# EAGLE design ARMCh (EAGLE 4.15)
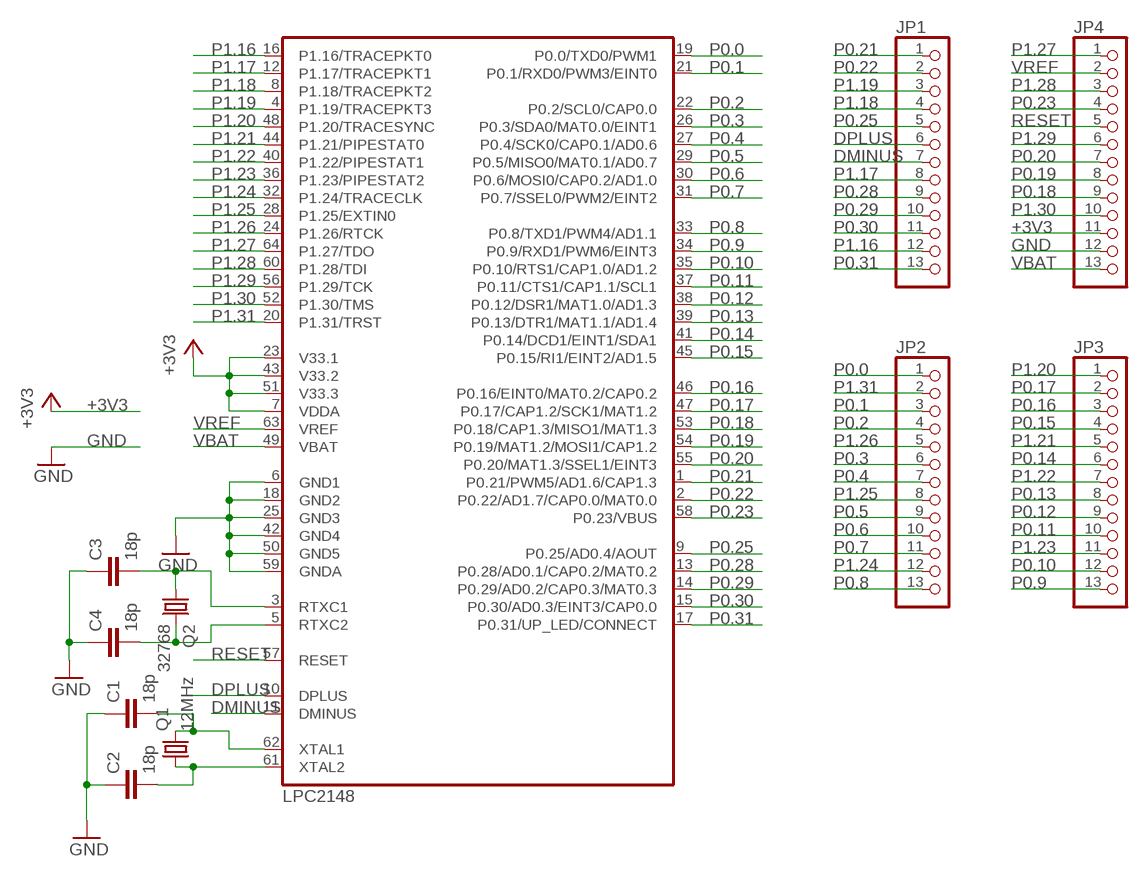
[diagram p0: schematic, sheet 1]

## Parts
C1  18p  C-EUC0805  [C0805]
C2  18p  C-EUC0805  [C0805]
C3  18p  C-EUC0805  [C0805]
C4  18p  C-EUC0805  [C0805]
JP1  PINHD-1X13  [1X13]
JP2  PINHD-1X13  [1X13]
JP3  PINHD-1X13  [1X13]
JP4  PINHD-1X13  [1X13]
LPC2148  LPC2146  [LQFP64]
Q1  12MHz  CRYTALHC49S  [HC49/S]
Q2  32768  CRYTALHC49U70  [HC49U70]

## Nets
+3V3: JP4.11 LPC2148.7(VDDA) LPC2148.23(V33.1) LPC2148.43(V33.2) LPC2148.51(V33.3)
DMINUS: JP1.7 LPC2148.11(DMINUS)
DPLUS: JP1.6 LPC2148.10(DPLUS)
GND: C1.1 C2.1 C3.1 C4.1 JP4.12 LPC2148.6(GND1) LPC2148.18(GND2) LPC2148.25(GND3) LPC2148.42(GND4) LPC2148.50(GND5) LPC2148.59(GNDA)
N$1: C1.2 LPC2148.62(XTAL1) Q1.2
N$3: C2.2 LPC2148.61(XTAL2) Q1.1
N$4: C3.2 LPC2148.3(RTXC1) Q2.1
N$5: C4.2 LPC2148.5(RTXC2) Q2.2
P0.0: JP2.1 LPC2148.19(P0.0/TXD0/PWM1)
P0.1: JP2.3 LPC2148.21(P0.1/RXD0/PWM3/EINT0)
P0.2: JP2.4 LPC2148.22(P0.2/SCL0/CAP0.0)
P0.3: JP2.6 LPC2148.26(P0.3/SDA0/MAT0.0/EINT1)
P0.4: JP2.7 LPC2148.27(P0.4/SCK0/CAP0.1/AD0.6)
P0.5: JP2.9 LPC2148.29(P0.5/MISO0/MAT0.1/AD0.7)
P0.6: JP2.10 LPC2148.30(P0.6/MOSI0/CAP0.2/AD1.0)
P0.7: JP2.11 LPC2148.31(P0.7/SSEL0/PWM2/EINT2)
P0.8: JP2.13 LPC2148.33(P0.8/TXD1/PWM4/AD1.1)
P0.9: JP3.13 LPC2148.34(P0.9/RXD1/PWM6/EINT3)
P0.10: JP3.12 LPC2148.35(P0.10/RTS1/CAP1.0/AD1.2)
P0.11: JP3.10 LPC2148.37(P0.11/CTS1/CAP1.1/SCL1)
P0.12: JP3.9 LPC2148.38(P0.12/DSR1/MAT1.0/AD1.3)
P0.13: JP3.8 LPC2148.39(P0.13/DTR1/MAT1.1/AD1.4)
P0.14: JP3.6 LPC2148.41(P0.14/DCD1/EINT1/SDA1)
P0.15: JP3.4 LPC2148.45(P0.15/RI1/EINT2/AD1.5)
P0.16: JP3.3 LPC2148.46(P0.16/EINT0/MAT0.2/CAP0.2)
P0.17: JP3.2 LPC2148.47(P0.17/CAP1.2/SCK1/MAT1.2)
P0.18: JP4.9 LPC2148.53(P0.18/CAP1.3/MISO1/MAT1.3)
P0.19: JP4.8 LPC2148.54(P0.19/MAT1.2/MOSI1/CAP1.2)
P0.20: JP4.7 LPC2148.55(P0.20/MAT1.3/SSEL1/EINT3)
P0.21: JP1.1 LPC2148.1(P0.21/PWM5/AD1.6/CAP1.3)
P0.22: JP1.2 LPC2148.2(P0.22/AD1.7/CAP0.0/MAT0.0)
P0.23: JP4.4 LPC2148.58(P0.23/VBUS)
P0.25: JP1.5 LPC2148.9(P0.25/AD0.4/AOUT)
P0.28: JP1.9 LPC2148.13(P0.28/AD0.1/CAP0.2/MAT0.2)
P0.29: JP1.10 LPC2148.14(P0.29/AD0.2/CAP0.3/MAT0.3)
P0.30: JP1.11 LPC2148.15(P0.30/AD0.3/EINT3/CAP0.0)
P0.31: JP1.13 LPC2148.17(P0.31/UP_LED/CONNECT)
P1.16: JP1.12 LPC2148.16(P1.16/TRACEPKT0)
P1.17: JP1.8 LPC2148.12(P1.17/TRACEPKT1)
P1.18: JP1.4 LPC2148.8(P1.18/TRACEPKT2)
P1.19: JP1.3 LPC2148.4(P1.19/TRACEPKT3)
P1.20: JP3.1 LPC2148.48(P1.20/TRACESYNC)
P1.21: JP3.5 LPC2148.44(P1.21/PIPESTAT0)
P1.22: JP3.7 LPC2148.40(P1.22/PIPESTAT1)
P1.23: JP3.11 LPC2148.36(P1.23/PIPESTAT2)
P1.24: JP2.12 LPC2148.32(P1.24/TRACECLK)
P1.25: JP2.8 LPC2148.28(P1.25/EXTIN0)
P1.26: JP2.5 LPC2148.24(P1.26/RTCK)
P1.27: JP4.1 LPC2148.64(P1.27/TDO)
P1.28: JP4.3 LPC2148.60(P1.28/TDI)
P1.29: JP4.6 LPC2148.56(P1.29/TCK)
P1.30: JP4.10 LPC2148.52(P1.30/TMS)
P1.31: JP2.2 LPC2148.20(P1.31/TRST)
RESET: JP4.5 LPC2148.57(RESET)
VBAT: JP4.13 LPC2148.49(VBAT)
VREF: JP4.2 LPC2148.63(VREF)

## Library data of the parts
C1-C4 = rcl:C-EU: CAPACITOR, European symbol
JP1-JP4 = pinhead:PINHD-1X13: PIN HEADER
LPC2148 = lpc2148:LPC2146: Philips LPC2146 ARM7
Q1 Q2 = crystal:CRYTAL: CRYSTAL

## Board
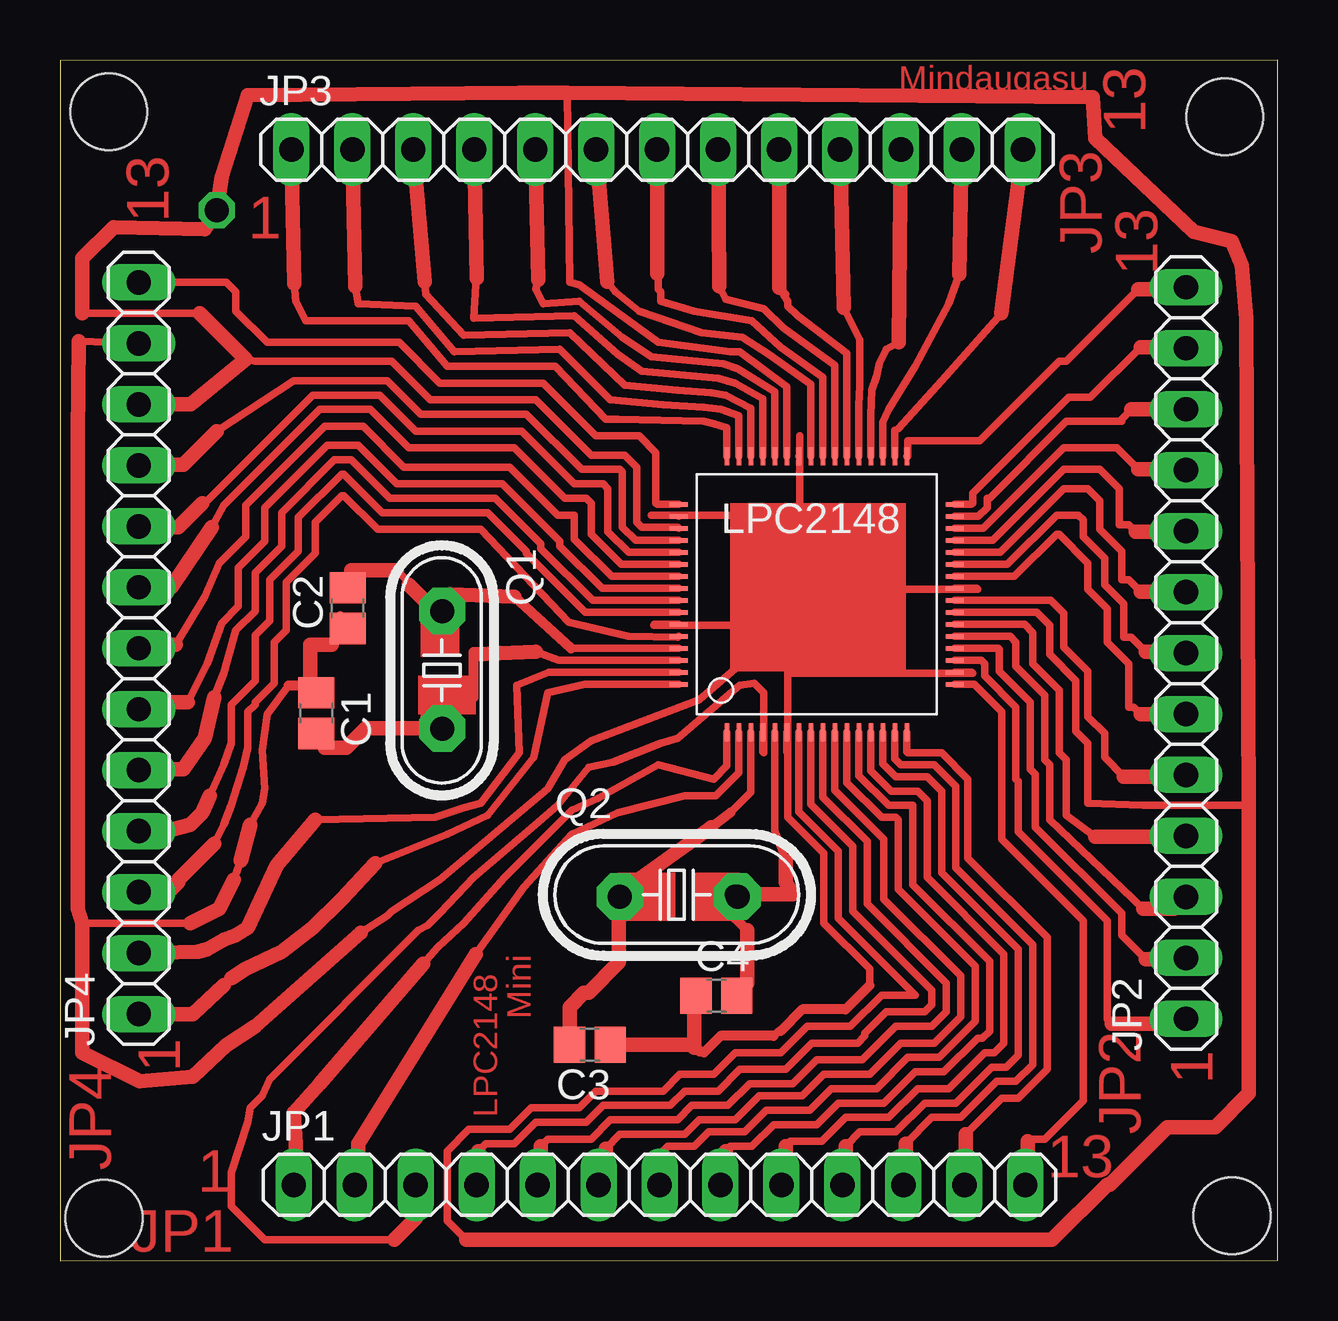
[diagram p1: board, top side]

Size 50.73 x 50.03 mm. Coordinates in mm from the lower left corner, seen from the top.
Outline: 0,0 50.73,0.03 50.73,50.03 0,50 0,0
Copper layers (1*16): Top 0.035mm / dielectric 1.5mm / Bottom 0.035mm
Design rules "default": minimum track width 10mil, minimum drill 24mil, track to track 8mil, track to pad 8mil, pad to pad 8mil, via to via 8mil, smd to smd 8mil, copper to edge 40mil, drill to drill 8mil, minimum pad ring 10mil, minimum via ring 8mil, stop-mask expansion 4mil, vias tented up to drill 0mil, thermal gap 10mil
Holes 3.2 mm at 2.03,47.87 48.53,47.67 48.83,1.87 1.83,1.77

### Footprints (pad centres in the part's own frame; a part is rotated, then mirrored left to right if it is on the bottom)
C0805 = smd 1.3 x 1.5: 1 -0.85,0; 2 0.85,0
1X13 = drill 1.016 long: 1 -15.24,0; 2 -12.7,0; 3 -10.16,0; 4 -7.62,0; 5 -5.08,0; 6 -2.54,0; 7 0,0; 8 2.54,0; 9 5.08,0; 10 7.62,0; 11 10.16,0; 12 12.7,0; 13 15.24,0
LQFP64 = smd 0.2 x 0.75: 1 -3.75,-5.75; 2 -3.25,-5.75; 3 -2.75,-5.75; 4 -2.25,-5.75; 5 -1.75,-5.75; 6 -1.25,-5.75; 7 -0.75,-5.75; 8 -0.25,-5.75; 9 0.25,-5.75; 10 0.75,-5.75; 11 1.25,-5.75; 12 1.75,-5.75; 13 2.25,-5.75; 14 2.75,-5.75; 15 3.25,-5.75; 16 3.75,-5.75; 33 3.75,5.75; 34 3.25,5.75; 35 2.75,5.75; 36 2.25,5.75; 37 1.75,5.75; 38 1.25,5.75; 39 0.75,5.75; 40 0.25,5.75; 41 -0.25,5.75; 42 -0.75,5.75; 43 -1.25,5.75; 44 -1.75,5.75; 45 -2.25,5.75; 46 -2.75,5.75; 47 -3.25,5.75; 48 -3.75,5.75 | smd 0.75 x 0.2: 17 5.75,-3.75; 18 5.75,-3.25; 19 5.75,-2.75; 20 5.75,-2.25; 21 5.75,-1.75; 22 5.75,-1.25; 23 5.75,-0.75; 24 5.75,-0.25; 25 5.75,0.25; 26 5.75,0.75; 27 5.75,1.25; 28 5.75,1.75; 29 5.75,2.25; 30 5.75,2.75; 31 5.75,3.25; 32 5.75,3.75; 49 -5.75,3.75; 50 -5.75,3.25; 51 -5.75,2.75; 52 -5.75,2.25; 53 -5.75,1.75; 54 -5.75,1.25; 55 -5.75,0.75; 56 -5.75,0.25; 57 -5.75,-0.25; 58 -5.75,-0.75; 59 -5.75,-1.25; 60 -5.75,-1.75; 61 -5.75,-2.25; 62 -5.75,-2.75; 63 -5.75,-3.25; 64 -5.75,-3.75
HC49/S = drill 0.813 round: 1 -2.413,0; 2 2.413,0
HC49U70 = drill 0.813 round: 1 -2.413,0; 2 2.413,0

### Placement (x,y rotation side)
C1  10.68,22.82 270 top
C2  11.98,27.19 90 top
C3  22.08,9 180 top
C4  27.35,11.04 0 top
JP1  24.98,3.16 0 top
JP2  46.92,25.32 90 top
JP3  24.88,46.3 0 top
JP4  3.28,25.52 90 top
LPC2148  31.54,27.76 0 top
Q1  15.91,24.6 270 top
Q2  25.7,15.25 0 top

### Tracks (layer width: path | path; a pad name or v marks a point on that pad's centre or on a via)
+3V3  (via drill 1)
  Top 0.305: LPC2148.7 30.79,18.71 32.43,17.07 32.43,14.27 35.63,11.07 34.23,11.07 32.93,9.77 31.13,9.77 30.03,8.67 28.13,8.67 27.23,7.77 25.83,7.77 25.13,7.07 22.33,7.07 21.63,6.37 19.63,6.37 18.73,5.47 17.03,5.47 16.13,4.57 16.13,1.67 16.93,0.87 | 43.63,3.17 43.73,3.17 | 49.53,18.97 45.13,18.97 42.83,19.07 42.83,21.57 42.33,22.07 42.33,24.17 41.23,25.27 41.23,26.47 40.69,27.01 LPC2148.23 | LPC2148.43 30.29,36.41 28.33,37.87 27.93,37.87 24.93,38.27 21.63,40.67 21.23,40.77 21.13,48.67 | LPC2148.51 25.73,30.57 24.23,30.57 24.03,30.77 24.03,33.07 23.53,33.57 22.13,33.57 19.83,35.87 15.43,35.87 13.83,37.47 8.13,37.47 7.73,37.57 | 0.93,39.47 5.83,39.47
  Top 0.61: 16.93,0.87 41.33,0.87 43.63,3.17 | 43.73,3.17 46.13,5.57 48.13,5.57 49.53,6.97 49.53,18.97 49.43,39.27 49.23,41.47 48.83,42.47 47.23,42.87 43.13,46.77 43.03,48.47 21.13,48.67 19.13,48.67 7.83,48.57 6.73,45.17 v6.53,43.77 6.03,42.97 2.23,43.07 0.93,41.77 0.93,39.47 | JP4.11 5.44,35.68 7.73,37.57 5.83,39.47
DMINUS
  Top 0.305: LPC2148.11 32.79,19.91 34.23,18.47 34.83,18.47 34.93,18.37 34.93,15.47 38.13,12.27 38.13,9.97 36.63,8.47 35.33,8.47 34.03,7.17 32.13,7.17 31.23,6.27 29.43,6.27 28.53,5.37 27.03,5.37 26.43,4.77 25.33,4.77 24.93,4.37 | 24.93,3.17 24.94,3.16 JP1.7
  Top 0.61: 24.93,3.17 24.93,4.37
DPLUS
  Top 0.305: LPC2148.10 32.29,19.61 34.33,17.57 34.33,15.07 37.53,11.87 37.53,10.17 36.43,9.07 35.03,9.07 33.73,7.77 31.83,7.77 30.93,6.87 29.13,6.87 28.13,5.87 26.63,5.87 26.03,5.27 23.33,5.27 22.73,4.67 | JP1.6 22.73,3.47
  Top 0.61: 22.73,3.47 22.73,4.67
GND
  Top 0.305: LPC2148.18 37.99,24.51 38.03,24.47 30.33,24.47 | 30.33,24.47 30.33,21.17 | 30.33,24.47 30.33,26.37 30.23,26.47 | 28.13,26.47 30.23,26.47 | 30.23,26.47 30.33,26.47 30.33,27.97 | 30.33,27.97 30.33,30.17 30.83,30.67 30.83,31.07 | 30.83,31.07 30.83,33.47 | 30.83,31.07 25.83,31.07 | LPC2148.25 38.19,28.01 38.23,27.97 30.33,27.97 | 25.83,31.07 25.79,31.03 LPC2148.50 | 25.83,31.07 24.63,31.07 | 30.83,33.47 LPC2148.42 | 30.83,33.47 30.83,34.37 | LPC2148.6 30.29,21.21 30.33,21.17 | 30.33,21.17 30.33,18.47 31.83,16.97 31.83,14.07 33.73,12.17 33.73,11.47 | 30.03,9.57 29.93,9.57 29.73,9.37 | 26.83,8.67 26.63,8.67 26.58,8.72 | 26.58,8.72 26.43,8.87 | C4.1 26.5,11 26.53,10.97 26.43,10.87 | LPC2148.59 24.77,26.51 24.73,26.47 28.13,26.47 | 26.58,8.72 26.63,8.77 | 0.78,38.32 JP4.12 | 0.93,14.07 5.43,14.07 | 7.23,15.87 7.53,16.67 | 7.93,18.17 8.43,19.07 8.53,19.67 8.43,21.27 8.63,22.77 9.53,23.97 | C1.1 10.73,23.67 10.43,23.97 | 11.68,26.92 C2.1 11.98,26.32 11.33,25.67 | 28.13,26.47 28.13,24.67 26.63,23.37 22.13,21.67 21.03,20.87 20.33,19.67 15.83,15.87 13.83,14.57 13.63,14.37 12.53,13.67
  Top 0.406: 33.73,11.47 32.73,10.47 30.93,10.47 30.03,9.57 | 29.73,9.37 27.53,9.37 26.83,8.67 | 26.63,8.77 26.4,9 | 9.53,23.97 10.43,23.97
  Top 0.61: 26.43,8.87 26.43,10.87 | 26.4,9 C3.1 | 0.78,38.32 0.73,34.37 0.73,14.67 0.93,14.07 0.93,8.67 3.33,7.47 5.53,7.67 6.93,8.97 8.13,9.77 12.53,13.67 | 5.43,14.07 6.63,14.67 7.23,15.87 | 7.53,16.67 7.93,18.17 | 10.43,23.97 10.43,25.67 11.33,25.67
N$1  (via drill 1 pad 1.93)
  Top 0.305: LPC2148.62 20.79,25.01 19.83,25.37 | 17.23,25.37 17.33,25.27 | Q1.2 v15.93,22.17 17.23,23.47 | C1.2 10.73,21.97 11.03,21.67 11.03,21.37
  Top 0.406: 17.23,23.47 17.23,25.37
  Top 0.61: 17.33,25.27 19.83,25.37 | Q1.2 12.75,22.19 11.93,21.37 11.03,21.37
N$2  (via drill 1 pad 1.93)
  other vias: 23.33,15.17
N$3  (via drill 1 pad 1.93)
  Top 0.305: 21.29,25.51 LPC2148.61 | 16.23,27.77 16.23,27.37 v15.93,27.07 15.91,27.05 Q1.1 15.69,27.01 | 14.53,28.17 14.53,28.27 14.03,28.77 | C2.2 12,28.04 12.13,28.17 12.13,28.77
  Top 0.406: 18.93,27.67 21.29,25.51
  Top 0.61: 16.23,27.77 18.93,27.67 | 14.53,28.17 15.69,27.01 | 12.13,28.77 14.03,28.77
N$4
  Top 0.305: C3.2 21.26,9 21.33,9.07 21.23,9.17 | LPC2148.3 28.79,19.53 27.93,18.67 | 23.23,15.27 23.25,15.25 Q2.1
  Top 0.406: 27.13,18.07 27.93,18.67
  Top 0.61: Q2.1 23.29,12.43 22.03,11.17 21.83,11.17 21.23,10.57 21.23,9.17 | 23.23,15.27 27.13,18.07
N$5
  Top 0.305: LPC2148.5 29.79,17.91 30.23,16.67 | 28.23,15.27 28.21,15.25 Q2.2 28.11,14.29 | C4.2 28.2,11.14 28.63,11.57
  Top 0.406: 28.63,13.77 28.11,14.29
  Top 0.61: 30.23,16.67 30.23,15.77 30.53,15.27 28.23,15.27 | 28.63,11.57 28.63,13.77
N$6  (via drill 1 pad 1.93)
  other vias: 28.23,15.17
P0.0
  Top 0.305: LPC2148.19 38.39,25.01 38.53,24.87 38.53,24.37 39.83,23.07 39.83,20.07 39.93,19.97 39.93,17.87 43.63,14.17 43.63,10.07 43.83,9.87 | JP2.1 46.73,9.87
  Top 0.61: 43.83,9.87 46.73,9.87
P0.1
  Top 0.305: LPC2148.21 39.59,26.01 39.83,25.77 39.83,24.77 41.03,23.57 41.03,20.87 41.23,20.67 41.23,18.37 45.13,14.67
  Top 0.61: 45.13,14.67 46.43,14.67 JP2.3
P0.2
  Top 0.305: LPC2148.22 40.19,26.51 40.53,26.17 40.53,24.87 41.63,23.77 41.63,21.17 41.93,20.87 41.93,18.57 43.13,17.67 | 47.03,17.67 47,17.7 JP2.4
  Top 0.61: 43.13,17.67 47.03,17.67
P0.3
  Top 0.305: LPC2148.26 39.77,28.51 41.53,30.27 41.63,30.27 42.83,29.07 42.83,27.97 43.63,27.17 43.63,25.77 44.53,24.87 44.53,23.07 44.73,23.07 45.03,22.77 | 46.83,22.77 46.84,22.78 JP2.6
  Top 0.61: 45.03,22.77 46.83,22.77
P0.4
  Top 0.305: LPC2148.27 39.47,29.01 41.53,31.07 42.43,31.07 42.63,30.87 42.63,30.17 43.53,29.27 43.53,28.17 44.33,27.37 44.33,25.97 44.63,25.97 45.23,25.37 | 46.83,25.37 46.88,25.32 JP2.7
  Top 0.61: 45.23,25.37 46.83,25.37
P0.5
  Top 0.305: LPC2148.29 38.87,30.01 41.83,32.97 43.33,32.97 44.13,32.17 44.13,30.67 44.53,30.67 44.83,30.37 | 46.93,30.37 46.92,30.38 JP2.9
  Top 0.61: 44.83,30.37 46.93,30.37
P0.6
  Top 0.305: LPC2148.30 38.47,30.51 41.83,33.87 44.03,33.87 44.93,32.97 | 46.93,32.97 46.92,32.96 JP2.10
  Top 0.61: 44.93,32.97 46.93,32.97
P0.7
  Top 0.305: LPC2148.31 38.27,31.01 38.63,31.37 38.63,31.77 38.73,31.77 41.93,34.97 44.23,34.97 44.23,35.07 44.63,35.47 | JP2.11
  Top 0.61: 44.63,35.47 JP2.11
P0.8
  Top 0.305: LPC2148.33 35.33,33.51 35.33,34.17 38.33,34.17 41.63,37.47 41.93,37.47 44.93,40.47 | JP2.13 46.83,40.47
  Top 0.61: 44.93,40.47 46.83,40.47
P0.9
  Top 0.305: LPC2148.34 34.79,34.61 34.93,34.67 36.73,36.67 39.23,39.47 39.22,39.48 39.23,39.57
  Top 0.61: 39.22,39.48 JP3.13
P0.10
  Top 0.305: LPC2148.35 34.29,34.93 34.53,35.47 35.63,37.27 37.03,39.87 37.46,41.1
  Top 0.61: 37.46,41.1 JP3.12
P0.11
  Top 0.305: LPC2148.37 33.29,35.63 33.33,36.47 33.33,38.37 32.66,39.7
  Top 0.61: 32.66,39.7 JP3.10
P0.12
  Top 0.305: LPC2148.38 32.79,37.81 30.73,39.37 30.33,39.77 30.33,39.97 29.96,40.54 30.23,40.27
  Top 0.61: 29.96,40.54 JP3.9
P0.13
  Top 0.305: LPC2148.39 32.29,37.31 30.13,38.87 29.33,39.67 27.73,40.07 27.46,40.6
  Top 0.61: 27.46,40.6 JP3.8
P0.14
  Top 0.305: LPC2148.41 31.29,36.51 29.53,37.77 28.43,38.47 26.73,38.67 24.13,39.57 23.13,40.37 22.8,40.8
  Top 0.61: 22.8,40.8 JP3.6
P0.15
  Top 0.305: LPC2148.45 29.29,35.91 28.13,36.57 27.43,36.77 24.23,37.07 23.23,37.77 21.43,39.37 17.23,39.27 17.33,40.67 17.33,40.87 17.36,40.94
  Top 0.61: 17.36,40.94 JP3.4
P0.16
  Top 0.305: LPC2148.46 28.79,35.51 27.73,36.07 27.13,36.17 25.73,36.27 23.53,36.47 21.23,38.67 16.83,38.57 15.23,40.27 15.2,40.8
  Top 0.61: 15.2,40.8 JP3.3
P0.17
  Top 0.305: LPC2148.47 28.29,35.21 27.53,35.47 26.83,35.57 25.13,35.67 22.93,35.87 20.83,37.97 16.43,37.87 14.83,39.77 12.43,39.87 12.3,40.6
  Top 0.61: 12.3,40.6 JP3.2
P0.18
  Top 0.305: LPC2148.53 23.69,29.51 22.83,30.37 22.83,32.17 22.63,32.37 21.43,32.37 19.23,34.57 14.83,34.57 13.33,36.07 10.53,36.07 6.03,31.57 5.93,31.57 | JP4.9 3.28,30.62 3.33,30.67 3.43,30.57
  Top 0.61: 5.93,31.57 4.93,30.57 3.43,30.57
P0.19
  Top 0.305: LPC2148.54 23.39,29.01 22.13,30.27 22.13,31.57 21.93,31.77 21.03,31.77 18.93,33.87 14.53,33.87 12.93,35.47 10.83,35.47 6.83,31.47 6.33,30.57 | 3.43,28.07 3.42,28.06 JP4.8
  Top 0.61: 6.33,30.57 4.63,28.07 3.43,28.07
P0.20
  Top 0.305: LPC2148.55 22.99,28.51 21.43,30.07 21.43,31.07 20.73,31.07 18.73,33.07 14.33,33.07 12.63,34.77 11.03,34.77 7.73,31.47 7.73,30.17 6.63,29.07 6.03,27.67 4.83,25.67 | 3.23,25.47 JP4.7 3.43,25.67
  Top 0.61: 3.43,25.67 4.83,25.67
P0.21
  Top 0.305: LPC2148.1 27.79,20.63 27.23,20.07 24.93,20.67 22.43,19.27 21.33,18.77 18.53,15.97 16.83,14.07 15.73,13.07 15.13,12.37 | 9.74,3.08 9.73,3.07 | JP1.1 9.74,3.08 | 9.74,3.08 9.83,3.17
  Top 0.61: 15.13,12.37 10.83,7.37 9.73,6.17 9.83,4.87 9.83,3.17
P0.22
  Top 0.305: LPC2148.2 28.29,20.33 27.33,19.37 26.03,19.37 23.23,18.67 21.33,17.77 19.33,15.57 17.33,12.77 | JP1.2 12.24,3.16 12.23,3.17 12.43,3.37
  Top 0.61: 17.33,12.77 12.43,4.87 12.43,3.37
P0.23
  Top 0.305: LPC2148.58 21.89,27.01 19.43,29.47 19.43,29.57 17.83,31.17 13.43,31.17 11.83,32.77 11.73,32.77 9.93,30.97 9.93,29.57 8.73,28.37 8.73,26.67 8.13,26.07 8.13,24.17 7.13,23.17 7.13,21.57 6.83,20.67 6.23,19.37 | JP4.4 3.3,17.9 3.53,17.67
  Top 0.61: 6.23,19.37 5.93,18.67 5.43,18.17 3.53,17.67
P0.25
  Top 0.305: LPC2148.9 31.79,19.31 33.63,17.47 33.63,14.87 36.93,11.57 36.93,10.37 36.33,9.77 34.83,9.77 33.43,8.37 31.53,8.37 30.53,7.37 28.73,7.37 27.83,6.47 26.33,6.47 25.73,5.87 22.93,5.87 22.13,5.07 20.33,5.07 20.03,4.77 | 19.93,3.67 20.03,3.77 | 19.93,3.17 19.92,3.16 JP1.5
  Top 0.61: 20.03,3.77 20.03,4.77 | 19.93,3.17 19.93,3.67
P0.28
  Top 0.305: LPC2148.13 33.79,20.41 34.63,19.57 35.73,19.57 36.13,19.17 36.13,15.97 39.33,12.77 39.33,9.07 38.93,8.67 38.53,8.67 37.03,7.17 35.73,7.17 34.53,5.97 32.73,5.97 31.73,4.97 30.43,4.97 30.23,4.77 | 30.06,3.1 30.03,3.07 | JP1.9 30.06,3.1 | 30.06,3.1 30.23,3.27
  Top 0.61: 30.23,3.27 30.23,4.77
P0.29
  Top 0.305: LPC2148.14 34.29,20.71 34.83,20.17 36.13,20.17 36.73,19.57 36.73,16.17 39.93,12.97 39.93,8.57 39.43,8.07 38.83,8.07 37.33,6.57 36.03,6.57 34.83,5.37 33.33,5.37 32.73,4.77 | 32.6,3.14 32.53,3.07 | JP1.10 32.6,3.14 | 32.6,3.14 32.73,3.27
  Top 0.61: 32.73,3.27 32.73,4.77
P0.30
  Top 0.305: LPC2148.15 34.79,20.91 35.03,20.67 36.43,20.67 37.33,19.77 37.33,16.37 40.53,13.17 40.53,8.17 39.83,7.47 39.03,7.47 37.53,5.97 36.33,5.97 35.23,4.87 | 35.14,3.08 35.13,3.07 | JP1.11 35.14,3.08 | 35.14,3.08 35.23,3.17
  Top 0.61: 35.23,3.17 35.23,4.87
P0.31
  Top 0.305: LPC2148.17 38.09,24.01 39.23,22.87 39.23,17.57 42.63,14.17 42.63,6.67 41.03,5.07 40.43,5.07 40.33,4.97 | JP1.13 40.33,3.27
  Top 0.61: 40.33,3.27 40.33,4.97
P1.16
  Top 0.305: LPC2148.16 35.29,21.21 35.33,21.17 36.73,21.17 37.83,20.07 37.83,16.77 41.13,13.47 41.13,7.97 39.93,6.77 39.23,6.77 37.73,5.27 | 37.68,3.12 37.63,3.07 | JP1.12 37.68,3.12 | 37.68,3.12 37.73,3.17
  Top 0.61: 37.73,3.17 37.73,5.27
P1.17
  Top 0.305: LPC2148.12 33.29,20.21 34.53,18.97 35.53,18.97 35.53,15.67 38.73,12.47 38.73,9.57 38.43,9.27 38.23,9.27 36.83,7.87 35.63,7.87 34.33,6.57 32.43,6.57 31.53,5.67 29.73,5.67 28.83,4.77 27.93,4.77 27.73,4.57 | JP1.8 27.52,3.08 27.53,3.07 27.73,3.27
  Top 0.61: 27.73,3.27 27.73,4.57
P1.18
  Top 0.305: LPC2148.8 31.29,19.01 33.03,17.27 33.03,14.57 36.33,11.27 36.33,10.67 36.03,10.37 34.43,10.37 33.53,9.47 33.53,9.37 33.23,9.07 31.33,9.07 30.23,7.97 28.33,7.97 27.43,7.07 26.03,7.07 25.43,6.47 22.63,6.47 21.93,5.77 19.83,5.77 18.93,4.87 17.73,4.87 17.43,4.57 | JP1.4 17.34,3.16 17.33,3.17 17.43,3.27
  Top 0.61: 17.43,3.27 17.43,4.57
P1.19
  Top 0.305: LPC2148.4 29.29,21.21 29.33,21.17 29.33,23.67 28.93,24.07 28.33,23.97 25.73,21.77 25.03,21.57 23.03,20.77 22.03,20.57 20.73,18.97 19.93,18.27 17.23,15.97 15.83,14.47 15.33,13.97 14.93,13.77 8.73,7.57 8.43,6.87 7.93,6.37 7.83,5.77 7.13,3.67 7.13,2.27 8.53,0.87 13.93,0.87 | JP1.3
  Top 0.61: 13.93,0.87 14.83,1.77 JP1.3
P1.20
  Top 0.305: LPC2148.48 27.79,34.71 27.23,34.87 26.83,34.97 23.23,35.07 22.73,35.07 20.63,37.27 16.13,37.27 14.53,39.17 10.23,39.17 9.83,39.97 9.76,40.7
  Top 0.61: 9.76,40.7 JP3.1
P1.21
  Top 0.305: LPC2148.44 29.79,36.21 28.23,37.17 27.63,37.37 24.63,37.67 23.43,38.47 21.63,39.97 20.13,39.87 19.83,40.47 19.93,40.87
  Top 0.61: 19.93,40.87 JP3.5
P1.22
  Top 0.305: LPC2148.40 31.79,36.81 30.03,38.07 28.83,39.17 26.43,39.57 25.03,39.97 25.03,40.37 24.93,40.47 24.93,40.87 24.88,41.12
  Top 0.61: 24.88,41.12 JP3.7
P1.23
  Top 0.305: LPC2148.36 33.79,35.23 33.83,36.27 34.03,36.87 34.13,37.37 34.43,37.97 34.94,38.28
  Top 0.61: 34.94,38.28 JP3.11
P1.24
  Top 0.305: LPC2148.32 37.97,31.51 38.03,31.57 38.03,31.97 42.03,35.97 42.93,35.97 45.03,38.07 | 46.83,38.07 46.88,38.02 JP2.12
  Top 0.61: 45.03,38.07 46.83,38.07
P1.25
  Top 0.305: LPC2148.28 39.17,29.51 41.83,32.17 42.83,32.17 43.33,31.67 43.33,30.47 44.23,29.57 44.23,28.37 44.53,28.37 45.03,27.87 | 46.83,27.87 46.84,27.86 JP2.8
  Top 0.61: 45.03,27.87 46.83,27.87
P1.26
  Top 0.305: LPC2148.24 41.29,27.51 41.83,26.97 41.83,25.57 42.83,24.57 42.83,22.67 43.53,21.97 43.53,20.97 44.33,20.17 | 46.93,20.27 46.92,20.26 | 46.92,20.26 JP2.5 | 46.83,20.17 46.92,20.26
  Top 0.61: 44.33,20.17 46.83,20.17
P1.27
  Top 0.305: LPC2148.64 21.87,24.01 20.33,23.67 19.73,20.97 17.83,18.57 16.13,17.77 13.13,16.57 | 6.83,11.47 7.13,11.77
  Top 0.61: 13.13,16.57 11.73,15.07 10.53,13.87 9.23,12.87 7.73,12.17 7.13,11.77 | 6.83,11.47 5.54,10.28 JP4.1
P1.28
  Top 0.305: LPC2148.60 25.73,25.97 23.67,26.01 21.19,26.61 17.53,30.47 13.23,30.47 11.83,31.87 11.73,31.87 10.63,30.77 10.63,29.47 9.43,28.27 9.43,26.27 8.93,25.77 8.93,24.07 8.13,23.27 8.13,23.17 7.83,22.87 7.83,21.37 7.63,20.57 7.13,18.97 6.83,18.17 6.43,17.37 | 4.93,15.77 4.93,15.87 | 3.33,15.37 3.32,15.36 JP4.3
  Top 0.61: 4.93,15.87 6.43,17.37 | 4.93,15.77 4.53,15.37 3.33,15.37
P1.29
  Top 0.305: LPC2148.56 22.59,28.01 20.83,29.77 20.83,29.97 18.43,32.37 14.03,32.37 12.43,33.97 11.13,33.97 8.53,31.37 8.53,29.97 7.43,28.87 7.43,27.27 6.73,26.57 6.13,24.87 5.33,23.27 | JP4.6 3.28,23.02 3.53,23.27
  Top 0.61: 3.53,23.27 5.33,23.27
P1.30
  Top 0.305: LPC2148.52 23.99,30.01 23.43,30.57 23.43,32.87 23.33,32.97 21.73,32.97 19.43,35.27 15.03,35.27 13.63,36.67 9.73,36.67 6.53,34.57 | 3.33,33.17 3.3,33.14 JP4.10
  Top 0.61: 6.53,34.57 5.13,33.17 3.33,33.17
P1.31
  Top 0.305: LPC2148.20 39.09,25.51 39.13,25.47 39.13,24.57 40.43,23.27 40.43,20.47 40.63,20.27 40.63,18.07 44.23,14.47 44.23,13.57 45.23,12.57 | 46.93,12.57 46.92,12.58 JP2.2
  Top 0.61: 45.23,12.57 46.93,12.57
RESET
  Top 0.305: LPC2148.57 22.19,27.51 20.03,29.67 20.03,29.87 18.13,31.77 13.73,31.77 12.13,33.37 11.43,33.37 9.23,31.17 9.23,29.77 8.13,28.67 8.13,27.07 7.33,26.27 6.83,24.47 6.43,23.47 | 3.33,20.47 3.3,20.44 JP4.5
  Top 0.61: 6.43,23.47 6.03,21.77 5.13,20.47 3.33,20.47
VBAT
  Top 0.305: LPC2148.49 24.89,31.51 24.83,31.57 24.83,33.67 24.13,34.37 22.33,34.37 20.13,36.57 15.83,36.57 14.13,38.27 8.63,38.27 7.33,39.57 7.33,40.37 6.93,40.77 3.33,40.77 3.32,40.76 JP4.13
VREF
  Top 0.305: LPC2148.63 20.37,24.51 19.03,23.97 19.13,21.17 17.53,19.07 16.83,18.87 15.63,18.47 10.63,18.37
  Top 0.61: 10.63,18.37 9.03,16.47 7.83,13.87 7.33,13.57 6.83,13.37 6.13,12.97 5.73,12.87 JP4.2
(copper drawn outside any net)
  shapes: Top area x7

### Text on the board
Top: Mindaugasu | JP3 | 13 | 1 | 13 | 13 | Mini | 1 | 1 | LPC2148 | JP2 | JP4 | 13 | 1 | JP1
